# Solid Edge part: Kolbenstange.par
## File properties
Username: bmolnar
Dokumentum tartalom típus: 0
Author: bmolnar
Last saved by: bmolnar
Revision: 78
Sűrűség: 0,000 kg/m^3
Pontosság: 0,990
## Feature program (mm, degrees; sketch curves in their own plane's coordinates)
base feature "unnamed BaseFeature 1"
sketch for "unnamed Protrusion 1" plane through (39.2, 0, 0) normal (1, 0, 0) x-axis (0, 0, -1)
  circle centre (0, 0) radius 25
extrude "unnamed Protrusion 1" add finite 17.6 along +normal
sketch for "Kihúzás_2" #1 plane through (39.2, 0, 0) normal (1, 0, 0) x-axis (0, 0, -1)
  circle centre (0, 0) radius 8
sketch for "Kihúzás_2" #2 plane through (39.2, 0, 0) normal (1, 0, 0) x-axis (0, 0, -1)
  circle centre (0, 0) radius 25
extrude "Kihúzás_2" add finite 9.4 along -normal
sketch for "Furat_1" plane through (3, 0, 0.0012) normal (-1, 0, 0) x-axis (0, 0, 1)
  hole centre (-0.0012, 0) bore radius 3.3235
hole "Furat_1" nominal diameter 8 finite  VBottomAngle = 118 deg; ThreadDepth = 14 mm
chamfer "Letörés_1" setback 0.7  SetBackValue2 = 45 deg
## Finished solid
Body 1: solid body, 16 faces, 22 edges, 11 vertices.
  Faces by surface: plane 8, cylinder 5, cone 2, torus 1
  Edges by curve: circle 12, line 6, curve on surface 2, ellipse 2
Bounding box of the edges (mm; curved faces can reach further): 56.800 x 50.000 x 50.000, from (0, -25, -25) to (56.8, 25, 25).
Cylindrical faces by radius (mm): R3.3235 x2, R4.125 x1, R8 x1, R25 x1
Conical faces (half-angle, radius in mm at the cone's reference point): 45 deg R4.0235 x1, 59 deg R3.3235 x1
Toroidal faces (ring radius, tube radius in mm): R6.2 r1.8 x1
Planar faces by outward normal: +x 1, +y 1, -x 3, -y 1, oblique 2
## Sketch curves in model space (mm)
circle centre (39.2, 0, 0) radius 25
circle centre (39.2, 0, 0) radius 8
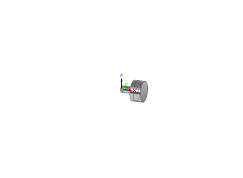
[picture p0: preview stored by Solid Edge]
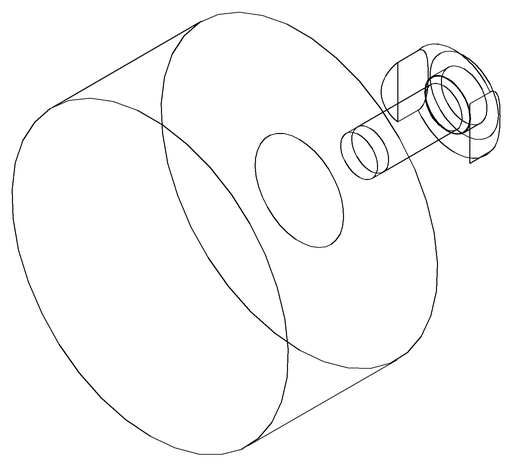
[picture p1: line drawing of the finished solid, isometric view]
